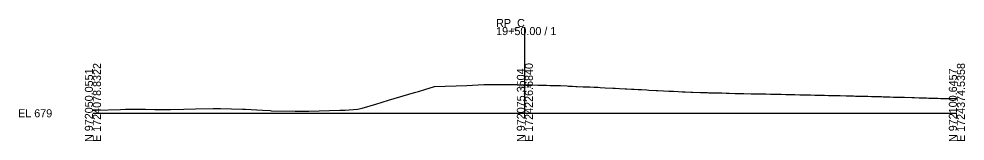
# Model space of a CAD drawing. Extents: x -26 to 1724616, y -10 to 972049.
# Drawn here: x -25.7 to 302.8, y 9490.3 to 9532.9 of the extents above; entities that cross this region are included whole.
import ezdxf

# ---------------------------------------------------------------- set-up
doc = ezdxf.new("R2010")
doc.units = 0
for name, color, linetype in [('Default', 7, 'Continuous'), ('Exist Cross Section Cell', 7, 'Continuous'), ('Exist XS Center Line Elevation Label', 7, 'Continuous'), ('Exist XS Ground Line', 7, 'Continuous')]:
    doc.layers.add(name, color=color, linetype=linetype)

msp = doc.modelspace()

# ---------------------------------------------------------------- linework, layer by layer
at = {"layer": 'Exist Cross Section Cell'}
for p, q in [((150, 9500), (150, 9530.01)), ((0, 9500), (150, 9500)), ((150, 9500), (300, 9500))]:
    msp.add_line(p, q, dxfattribs=at)
at = {"layer": 'Exist XS Ground Line'}
msp.add_lwpolyline([(0, 9501.12), (1.18, 9501.11), (9.62, 9501.29), (11.33, 9501.41), (18.28, 9501.45), (21.47, 9501.29), (26.94, 9501.35), (31.62, 9501.44), (35.61, 9501.56), (41.76, 9501.71), (44.27, 9501.66), (51.91, 9501.43), (52.93, 9501.44), (58.93, 9501.07), (61.6, 9500.91), (62.05, 9500.86), (70.26, 9500.69), (72.2, 9500.7), (74.93, 9500.73), (82.16, 9500.95), (85.79, 9501.03), (87.56, 9501.13), (91.91, 9501.45), (93.47, 9501.75), (98.28, 9503.14), (102.63, 9504.55), (111.65, 9507.27), (113.08, 9507.63), (115.25, 9508.27), (118.62, 9509.28), (129.8, 9509.67), (135.75, 9509.99), (137.24, 9510), (139.34, 9510), (139.74, 9510), (140.31, 9510), (142.33, 9510), (143.71, 9509.99), (144.88, 9509.98), (145.84, 9509.98), (147.39, 9509.96), (148.01, 9509.95), (150.18, 9509.91), (151.71, 9509.87), (152.46, 9509.85), (154.48, 9509.81), (155.02, 9509.8), (156.65, 9509.76), (157.52, 9509.74), (158.77, 9509.71), (160.07, 9509.68), (161.4, 9509.64), (162.39, 9509.61), (164.64, 9509.5), (165.13, 9509.48), (166.51, 9509.42), (167.71, 9509.37), (168.12, 9509.35), (170.27, 9509.26), (171.53, 9509.21), (172.49, 9509.16), (173.99, 9509.1), (175.28, 9509.03), (176.17, 9508.99), (177.82, 9508.91), (180.48, 9508.79), (181.35, 9508.75), (182.9, 9508.67), (184.83, 9508.56), (185.42, 9508.52), (187.01, 9508.43), (187.97, 9508.37), (189.32, 9508.3), (190.49, 9508.24), (192.38, 9508.14), (193.03, 9508.1), (195.55, 9507.98), (196.18, 9507.95), (198.11, 9507.84), (200.01, 9507.73), (200.66, 9507.69), (201.58, 9507.64), (203.19, 9507.57), (204.64, 9507.51), (205.7, 9507.46), (207.67, 9507.39), (208.23, 9507.36), (210.97, 9507.27), (213.35, 9507.19), (213.84, 9507.17), (215.87, 9507.12), (216.86, 9507.1), (218.39, 9507.07), (219.91, 9507.02), (220.92, 9506.99), (222.98, 9506.93), (223.46, 9506.92), (226.05, 9506.86), (228.54, 9506.8), (229.12, 9506.79), (231.08, 9506.75), (232.17, 9506.74), (233.61, 9506.71), (235.23, 9506.68), (236.15, 9506.66), (238.3, 9506.62), (238.95, 9506.61), (240.61, 9506.57), (241.37, 9506.55), (243.78, 9506.5), (245.48, 9506.47), (246.32, 9506.45), (246.7, 9506.44), (248.08, 9506.41), (249.16, 9506.38), (250.68, 9506.35), (251.62, 9506.33), (253.45, 9506.28), (254.06, 9506.27), (255.47, 9506.24), (256.73, 9506.21), (258.26, 9506.17), (259.43, 9506.14), (261.59, 9506.09), (262.18, 9506.07), (264.05, 9506.02), (264.78, 9506), (266.59, 9505.95), (269.12, 9505.9), (270.34, 9505.87), (271.76, 9505.84), (273.77, 9505.78), (274.39, 9505.76), (276.15, 9505.71), (276.72, 9505.7), (278.03, 9505.66), (279.25, 9505.63), (281.08, 9505.58), (281.78, 9505.56), (284.32, 9505.47), (285.23, 9505.44), (286.86, 9505.39), (288.8, 9505.34), (289.41, 9505.32), (290.27, 9505.29), (291.95, 9505.24), (293.33, 9505.2), (294.47, 9505.17), (296.38, 9505.14), (297, 9505.14), (299.54, 9505.12), (300, 9505.11)], dxfattribs=at)

# ---------------------------------------------------------------- texts
at = {"layer": 'Default'}
msp.add_text('-', height=0.0001, dxfattribs=at).set_placement((0, 9500))
at = {"layer": 'Exist Cross Section Cell'}
for s, p in [('RP_C', (140, 9530.01)), ('19+50.00 / 1', (140, 9527.21)), ('EL 679', (-26, 9498.6))]:
    msp.add_text(s, height=2.8, dxfattribs=at).set_placement(p)
for s, p in [('N 972050.0551', (0, 9490)), ('E 1724078.8322', (2.8, 9490)), ('N 972075.3504', (150, 9490)), ('E 1724226.6840', (152.8, 9490)), ('N 972100.6457', (300, 9490)), ('E 1724374.5358', (302.8, 9490))]:
    msp.add_text(s, height=2.8, rotation=90, dxfattribs=at).set_placement(p)
at = {"layer": 'Exist XS Center Line Elevation Label'}
msp.add_text('688.91', height=1, dxfattribs=at).set_placement((148, 9508.79))

doc.saveas('drawing.dxf')
